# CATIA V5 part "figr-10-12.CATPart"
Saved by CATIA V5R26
Part number: Part1
Bounding box of the stored display mesh (mm): x -100 to 0, y -100 to 90, z 0 to 33.63
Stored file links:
  D:\_Deepak\CATIA\CATIA V5-6R2016_Deepak\Resources\Part files\Partfiles\c10_catia_v5_6r2016_prt\figr-10-12.CATPart
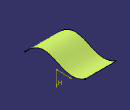
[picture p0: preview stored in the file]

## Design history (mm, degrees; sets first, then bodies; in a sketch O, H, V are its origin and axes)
Set1
  Sketch1 on face of yz-plane, origin (0, 0, 0), H (0, 0, -1), V (0, 1, 0)
    spline S1 through (0, -100) (-30, -20) (-10, 30) (-20, 90)
  Extrude1: Element1 Sketch1, Lim1 0, Lim2 100, Direction face of yz-plane
Body1 (main body)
